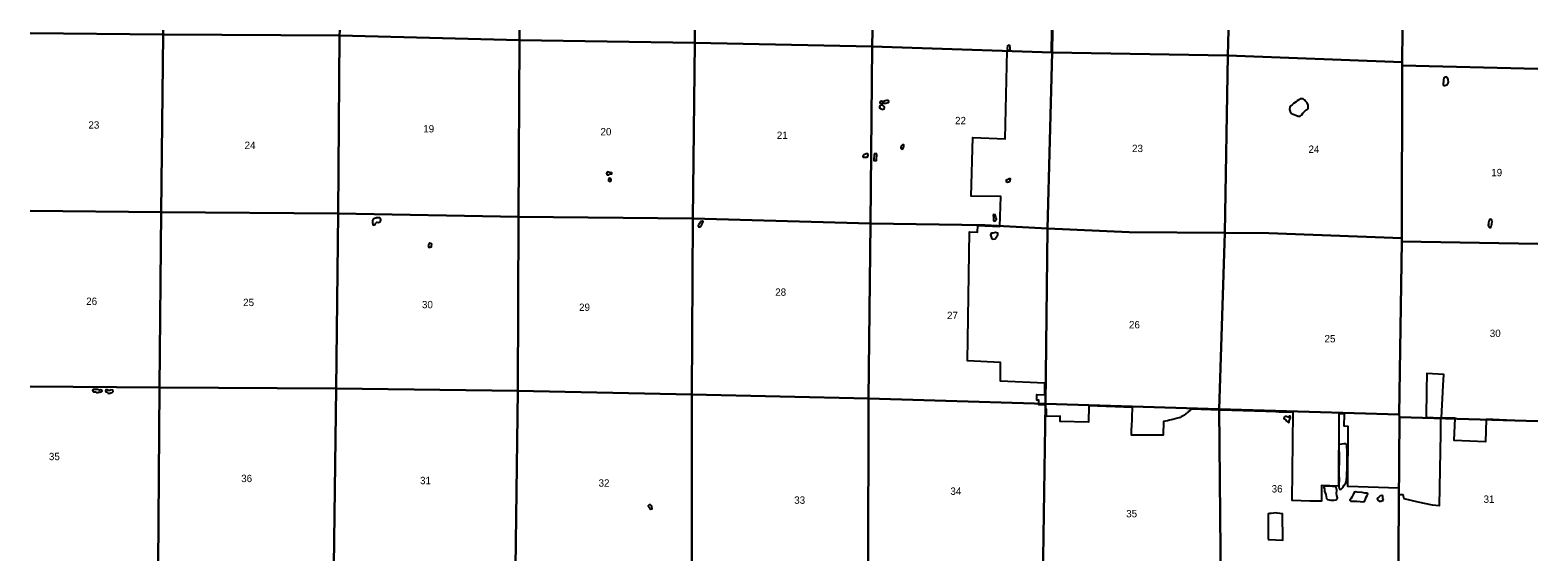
# Model space of a CAD drawing. Extents: x 0 to 680, y 0 to 834.
# Drawn here: x 44.7 to 374.7, y 720 to 834.1 of the extents above; entities that cross this region are included whole.
import ezdxf

# ---------------------------------------------------------------- set-up
doc = ezdxf.new("R2010")
doc.units = 0
for name, color, linetype in [('GM_X_Corporation', 7, 'Continuous'), ('GM_X_Minor_Lake', 7, 'Continuous'), ('GM_X_Section', 7, 'Continuous'), ('GM_X_Section_Text', 7, 'Continuous')]:
    doc.layers.add(name, color=color, linetype=linetype)

msp = doc.modelspace()

# ---------------------------------------------------------------- linework, layer by layer
at = {"layer": 'GM_X_Corporation'}
msp.add_lwpolyline([(374.69, 748.49), (370.8, 748.64), (364.86, 748.91), (363.38, 748.96), (363.24, 744.06), (356.4, 744.3), (356.57, 749.19), (353.64, 749.27), (353.97, 756.39), (354.14, 758.78), (350.37, 758.95), (350.31, 755.36), (350.23, 749.4), (353.42, 749.28), (353.38, 745.93), (353.13, 730.06), (351.66, 730.18), (348.5, 730.86), (345.45, 731.61), (345.23, 732.46), (344.3, 732.48), (344.29, 733.92), (333.13, 734.27), (333.21, 747.43), (332.3, 747.46), (332.35, 750.11), (331.14, 750.15), (331.08, 734.38), (327.36, 734.51), (327.35, 731.03), (324.8, 731.09), (320.94, 731.21), (321.13, 750.44), (318.09, 750.53), (317.35, 750.57), (315.12, 750.65), (305.2, 750.97), (298.92, 751.16), (298.7, 750.98), (298.54, 750.86), (298.43, 750.76), (298.31, 750.66), (298.19, 750.57), (298.07, 750.47), (297.96, 750.38), (297.84, 750.28), (297.76, 750.22), (297.76, 750.22), (297.72, 750.19), (297.57, 750.07), (297.42, 749.95), (297.32, 749.89), (296.62, 749.49), (296.4, 749.39), (296.15, 749.3), (295.85, 749.21), (294.77, 748.92), (294.07, 748.75), (293.63, 748.65), (293.21, 748.55), (292.79, 748.46), (292.69, 745.49), (285.72, 745.47), (285.75, 747.12), (285.86, 747.14), (285.94, 751.52), (276.4, 751.93), (276.36, 748.36), (270.11, 748.52), (270.12, 749.67), (267.14, 749.59), (267.15, 751.18), (267.02, 751.18), (267.01, 752.1), (266.8, 752.11), (266.51, 752.1), (265.44, 752.12), (265.45, 753.13), (265.05, 753.15), (265.06, 754.38), (266.81, 754.3), (266.82, 756.9), (257.09, 757.28), (257.11, 761.4), (249.87, 761.75), (250.31, 789.95), (252.07, 789.89), (252.1, 791.35), (256.94, 791.17), (257.15, 797.7), (250.65, 797.8), (251.06, 810.58), (258.09, 810.31), (258.51, 829.58), (268.24, 829.25), (268.3, 834.07)], dxfattribs=at)
at = {"layer": 'GM_X_Minor_Lake'}
for p, q in [((258.6, 830.34), (258.57, 830.25)), ((354.07, 822.94), (354.03, 822.76)), ((231.85, 818.6), (231.57, 818.49)), ((231.55, 817.38), (231.28, 817.66)), ((321.77, 818.38), (321.24, 818.02)), ((235.3, 808.64), (235.27, 808.48)), ((227.65, 807), (227.5, 806.93)), ((229.98, 807.06), (229.4, 807.05)), ((170.94, 802.43), (171.35, 802.4)), ((171.32, 801.6), (171.27, 801.35)), ((258.74, 801.5), (258.57, 801.37)), ((119.75, 792.77), (119.63, 792.43)), ((191.43, 792.23), (191.22, 791.78)), ((255.67, 793.76), (255.48, 793.66)), ((255.67, 789.77), (255.37, 789.68)), ((363.87, 791.95), (363.89, 791.66)), ((131.95, 787.3), (131.84, 786.95)), ((59.66, 755.41), (59.46, 755.47)), ((62.11, 755.28), (61.83, 755.27)), ((320.02, 749.45), (319.6, 749.57)), ((331.2, 740.65), (331.16, 737.08)), ((329.75, 734.25), (328.22, 734.31)), ((336.26, 732.95), (335.14, 733.05)), ((180.15, 729.75), (180.28, 729.6)), ((340.9, 731.29), (340.79, 731.64)), ((315.69, 725.51), (315.67, 722.66))]:
    msp.add_line(p, q, dxfattribs=at)
for points in [[(258.57, 830.25), (258.56, 829.95), (258.65, 829.78), (258.95, 829.66), (259.22, 829.86), (259.21, 830.26), (259.09, 830.71), (258.81, 830.82), (258.59, 830.62), (258.6, 830.34)], [(354.03, 822.76), (353.94, 822.44), (353.96, 822.17), (354.09, 821.99), (354.35, 821.97), (354.76, 822.09), (355.09, 822.55), (355.11, 822.68), (355.06, 823.26), (354.93, 823.68), (354.72, 823.83), (354.46, 823.82), (354.2, 823.71), (354.08, 823.52), (354.06, 823.2), (354.07, 822.94)], [(231.57, 818.49), (231.22, 818.46), (231.05, 818.53), (230.77, 818.46), (230.66, 818.21), (231.07, 818.1), (231.49, 818.12), (231.97, 818.1), (232.51, 818.25), (232.62, 818.5), (232.52, 818.67), (232.14, 818.71), (231.85, 818.6)], [(321.24, 818.02), (320.9, 817.74), (320.6, 817.51), (320.39, 817.21), (320.34, 816.74), (320.49, 816.27), (320.8, 815.87), (321.15, 815.69), (321.7, 815.47), (322.22, 815.27), (322.69, 815.29), (323.03, 815.58), (323.25, 815.91), (323.77, 816.43), (324.19, 816.73), (324.44, 817.03), (324.44, 817.66), (324.18, 818.19), (323.84, 818.53), (323.67, 818.74), (323.36, 819.02), (323.04, 819.07), (322.7, 819.02), (322.36, 818.86), (321.98, 818.59), (321.77, 818.38)], [(231.28, 817.66), (230.99, 817.69), (230.69, 817.52), (230.56, 817.32), (230.61, 817.07), (230.96, 816.88), (231.16, 816.74), (231.6, 816.89), (231.7, 817.18), (231.55, 817.38)], [(235.27, 808.48), (235.23, 808.23), (235.46, 808.04), (235.67, 808.13), (235.91, 808.64), (235.89, 808.96), (235.66, 808.98), (235.42, 808.81), (235.3, 808.64)], [(227.5, 806.93), (227.18, 806.82), (226.99, 806.66), (226.96, 806.47), (227.04, 806.31), (227.45, 806.29), (227.86, 806.27), (228.05, 806.48), (228.1, 806.73), (228.06, 807.01), (227.91, 807.04), (227.65, 807)], [(229.4, 807.05), (229.39, 805.57), (229.91, 805.54), (229.98, 807.06)], [(171.35, 802.4), (171.67, 802.63), (172.01, 802.68), (172, 802.84), (171.62, 802.95), (171.34, 803), (171.05, 803.07), (170.88, 802.98), (170.86, 802.79), (170.88, 802.6), (170.94, 802.43)], [(171.27, 801.35), (171.26, 801.11), (171.52, 800.99), (171.76, 801.04), (171.87, 801.37), (171.8, 801.55), (171.48, 801.7), (171.32, 801.6)], [(258.57, 801.37), (258.31, 801.24), (258.3, 800.95), (258.58, 800.8), (259.02, 800.97), (259.18, 801.2), (259.3, 801.54), (258.96, 801.59), (258.74, 801.5)], [(119.63, 792.43), (119.59, 792), (119.7, 791.68), (119.86, 791.45), (120.24, 791.56), (120.38, 791.87), (120.6, 792.09), (120.89, 792), (121.3, 792.15), (121.34, 792.31), (121.44, 792.54), (121.35, 792.88), (121.21, 793.04), (120.86, 793.03), (120.53, 793.02), (120.32, 792.98), (120.03, 792.87), (119.75, 792.77)], [(191.22, 791.78), (191.07, 791.6), (190.97, 791.47), (190.91, 791.27), (191.14, 791), (191.41, 791.1), (191.66, 791.42), (191.89, 791.88), (192.01, 792.24), (191.8, 792.33), (191.43, 792.23)], [(255.48, 793.66), (255.54, 792.95), (255.56, 792.41), (255.84, 792.3), (256.19, 792.74), (256.09, 793.09), (255.96, 793.47), (255.89, 793.67), (255.67, 793.76)], [(363.89, 791.66), (363.83, 791.44), (363.89, 791.18), (363.94, 791.03), (364.13, 790.91), (364.4, 790.94), (364.51, 791.26), (364.6, 791.58), (364.6, 791.74), (364.6, 791.86), (364.66, 792.14), (364.62, 792.45), (364.49, 792.69), (364.26, 792.71), (364.07, 792.48), (363.98, 792.2), (363.87, 791.95)], [(255.37, 789.68), (255.13, 789.66), (254.91, 789.3), (255.09, 788.64), (255.33, 788.37), (255.89, 788.41), (256.21, 788.86), (256.52, 789.31), (256.46, 789.66), (255.96, 789.85), (255.67, 789.77)], [(131.84, 786.95), (131.85, 786.74), (131.98, 786.55), (132.2, 786.61), (132.51, 786.69), (132.54, 787.07), (132.58, 787.29), (132.46, 787.42), (132.17, 787.51), (132.01, 787.38), (131.95, 787.3)], [(59.46, 755.47), (59.16, 755.47), (58.73, 755.5), (58.5, 755.47), (58.34, 755.33), (58.42, 755.09), (58.59, 754.95), (58.91, 754.94), (59.06, 754.94), (59.2, 754.86), (59.48, 754.83), (59.71, 754.88), (59.82, 754.97), (60.05, 754.91), (60.25, 754.95), (60.42, 755.15), (60.41, 755.37), (60.1, 755.39), (59.87, 755.33), (59.66, 755.41)], [(61.83, 755.27), (61.56, 755.4), (61.29, 755.38), (61.16, 755.13), (61.26, 755), (61.51, 754.95), (61.75, 754.69), (61.95, 754.64), (62.33, 754.74), (62.67, 754.86), (62.88, 755.05), (62.78, 755.31), (62.36, 755.41), (62.11, 755.28)], [(319.6, 749.57), (319.37, 749.6), (319.18, 749.47), (319.1, 749.18), (319.36, 748.97), (319.54, 748.84), (319.63, 748.62), (319.9, 748.43), (320.12, 748.25), (320.24, 748.34), (320.27, 748.59), (320.34, 748.9), (320.56, 749.32), (320.5, 749.67), (320.24, 749.64), (320.18, 749.46), (320.02, 749.45)], [(331.16, 737.08), (331.2, 735.59), (331.12, 734.86), (331.17, 734.23), (331.22, 733.88), (331.37, 733.65), (331.67, 733.69), (332.02, 734.05), (332.32, 734.58), (332.65, 735.06), (332.79, 735.54), (332.8, 735.8), (332.85, 736.36), (332.94, 738.79), (332.95, 741.71), (332.9, 743.37), (332.67, 743.61), (332.26, 743.58), (331.78, 743.55), (331.31, 743.49), (331.13, 743.26), (331.2, 740.65)], [(328.22, 734.31), (327.92, 734.3), (327.84, 734.08), (327.96, 733.72), (328.03, 733.23), (328.3, 732.55), (328.36, 732.08), (328.42, 731.63), (328.62, 731.42), (329.35, 731.3), (330.08, 731.27), (330.57, 731.36), (330.84, 731.83), (330.69, 732.28), (330.62, 732.73), (330.7, 733.46), (330.58, 734.07), (330.33, 734.26), (329.75, 734.25)], [(335.14, 733.05), (334.78, 733.08), (334.59, 733), (334.31, 732.69), (334.18, 732.4), (334, 731.96), (333.74, 731.6), (333.55, 731.29), (333.79, 731.07), (334.32, 731.06), (335.09, 731.05), (335.77, 730.98), (336.39, 730.95), (336.78, 731.02), (336.96, 731.49), (337.04, 731.72), (337.12, 731.95), (337.31, 732.29), (337.47, 732.58), (337.32, 732.83), (336.86, 732.84), (336.26, 732.95)], [(180.28, 729.6), (180.38, 729.37), (180.57, 729.29), (180.82, 729.37), (180.78, 729.96), (180.47, 730.27), (180.15, 730.23), (179.98, 730.04), (180.15, 729.75)], [(340.79, 731.64), (340.79, 731.69), (340.75, 732.19), (340.73, 732.2), (340.56, 732.28), (340.21, 732.24), (340.12, 732.16), (339.87, 731.92), (339.59, 731.71), (339.56, 731.57), (339.69, 731.27), (339.97, 731.03), (340.33, 731.07), (340.9, 731.29)], [(315.67, 722.66), (318.85, 722.57), (318.81, 728.33), (317.67, 728.44), (317.34, 728.5), (316.91, 728.47), (316.3, 728.4), (315.99, 728.35), (315.7, 728.32), (315.69, 725.51)]]:
    msp.add_lwpolyline(points, dxfattribs=at)
at = {"layer": 'GM_X_Section'}
for points in [[(73.84, 834.07), (73.83, 833.16), (44.69, 833.38)], [(44.69, 833.38), (73.83, 833.16), (73.34, 794.25), (44.69, 794.54)], [(112.44, 834.07), (112.43, 832.87), (73.83, 833.16), (73.84, 834.07)], [(151.79, 834.07), (151.79, 831.91), (112.43, 832.87), (112.44, 834.07)], [(190.17, 834.07), (190.17, 831.33), (151.79, 831.91), (151.79, 834.07)], [(229.04, 834.07), (229.01, 830.47), (190.17, 831.33), (190.17, 834.07)], [(268.45, 834.07), (268.39, 829.2), (229.01, 830.47), (229.04, 834.07)], [(306.95, 834.07), (306.83, 828.5), (268.39, 829.2), (268.45, 834.07)], [(345.05, 834.07), (345.01, 827.04), (306.83, 828.5), (306.95, 834.07)], [(374.69, 825.64), (345.03, 826.36), (345.01, 827.04), (345.05, 834.07)], [(374.69, 787.34), (344.9, 787.84), (344.9, 788.59), (345.03, 826.36), (374.69, 825.64)], [(44.69, 794.54), (73.34, 794.25), (73.02, 755.95), (44.69, 756.13)], [(374.69, 748.56), (344.39, 749.46), (344.34, 750), (344.9, 787.84), (374.69, 787.34)], [(44.69, 756.13), (73.02, 755.95), (72.69, 717.09), (44.69, 717.41)], [(374.69, 710.26), (344.09, 711.3), (344.39, 749.46), (374.69, 748.56)]]:
    msp.add_lwpolyline(points, dxfattribs=at)
for points in [[(73.83, 833.16), (112.43, 832.87), (112.09, 793.99), (73.34, 794.25)], [(112.43, 832.87), (151.79, 831.91), (151.57, 793.25), (112.09, 793.99)], [(151.79, 831.91), (190.17, 831.33), (189.71, 792.87), (151.57, 793.25)], [(190.17, 831.33), (229.01, 830.47), (228.6, 791.79), (189.71, 792.87)], [(229.01, 830.47), (268.39, 829.2), (267.34, 790.69), (253.66, 791.44), (228.6, 791.79)], [(268.39, 829.2), (306.83, 828.5), (306.15, 789.76), (285.25, 789.89), (267.34, 790.69)], [(306.83, 828.5), (345.01, 827.04), (345.03, 826.36), (344.9, 788.59), (315.78, 789.67), (306.15, 789.76)], [(112.09, 793.99), (111.68, 755.71), (73.02, 755.95), (73.34, 794.25)], [(112.09, 793.99), (151.57, 793.25), (151.41, 755.16), (111.68, 755.71)], [(151.57, 793.25), (189.71, 792.87), (189.5, 754.4), (151.41, 755.16)], [(189.71, 792.87), (228.6, 791.79), (228.16, 753.52), (189.5, 754.4)], [(228.6, 791.79), (253.66, 791.44), (267.34, 790.69), (266.9, 752.37), (228.16, 753.52)], [(267.34, 790.69), (285.25, 789.89), (306.15, 789.76), (304.96, 751.22), (266.9, 752.37)], [(306.15, 789.76), (315.78, 789.67), (344.9, 788.59), (344.9, 787.84), (344.34, 750), (304.96, 751.22)], [(73.02, 755.95), (111.68, 755.71), (111.16, 716.99), (72.69, 717.09)], [(111.68, 755.71), (151.41, 755.16), (150.89, 716.62), (150.15, 716.6), (111.16, 716.99)], [(151.41, 755.16), (189.5, 754.4), (189.54, 715.85), (188.47, 715.88), (150.89, 716.62)], [(228.16, 753.52), (228.14, 715.12), (227.12, 715.11), (189.54, 715.85), (189.5, 754.4)], [(266.9, 752.37), (266.32, 713.83), (228.14, 715.12), (228.16, 753.52)], [(266.9, 752.37), (304.96, 751.22), (305.27, 712.65), (266.32, 713.83)], [(304.96, 751.22), (344.34, 750), (344.39, 749.46), (344.09, 711.3), (305.27, 712.65)]]:
    msp.add_lwpolyline(points, close=True, dxfattribs=at)

# ---------------------------------------------------------------- texts
at = {"layer": 'GM_X_Section_Text'}
for s, p in [('22', (247.13, 813.5)), ('23', (57.44, 812.54)), ('19', (130.73, 811.71)), ('20', (169.53, 811.07)), ('21', (208.11, 810.28)), ('24', (91.63, 808.09)), ('23', (285.87, 807.41)), ('24', (324.49, 807.24)), ('19', (364.49, 802.13)), ('26', (56.96, 773.98)), ('28', (207.77, 775.98)), ('25', (91.31, 773.73)), ('30', (130.45, 773.25)), ('29', (164.83, 772.67)), ('27', (245.37, 770.88)), ('26', (285.2, 768.85)), ('25', (328, 765.79)), ('30', (364.17, 766.97)), ('35', (48.8, 740.03)), ('36', (90.89, 735.23)), ('31', (130.03, 734.78)), ('32', (169.1, 734.24)), ('34', (246.11, 732.45)), ('36', (316.43, 732.96)), ('33', (211.93, 730.49)), ('31', (362.81, 730.7)), ('35', (284.6, 727.53))]:
    msp.add_text(s, height=1.607, rotation=0, dxfattribs=at).set_placement(p)

doc.saveas('drawing.dxf')
